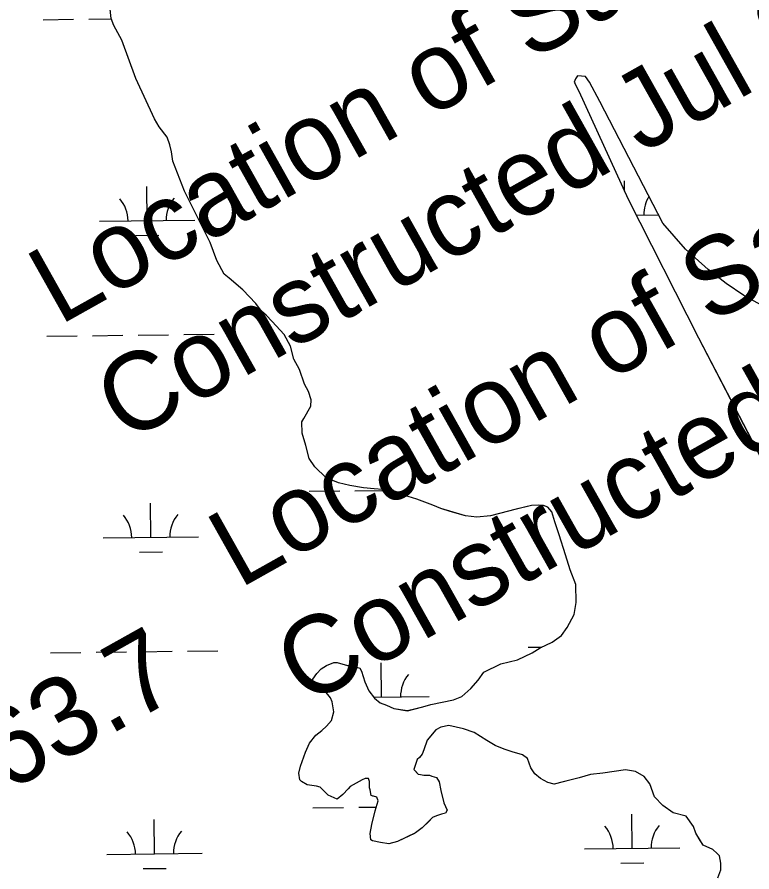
# Model space of a CAD drawing. Extents: x 3684037 to 3722149, y 433263 to 459021.
# Drawn here: x 3712807 to 3713579, y 440224 to 441123 of the extents above; entities that cross this region are included whole.
import ezdxf

# ---------------------------------------------------------------- set-up
doc = ezdxf.new("R2010")
doc.units = 0
for name, color, linetype in [('V-RIVR-RANG-IDEN', 7, 'Continuous'), ('V-RRAP-SILL-IDEN', 7, 'Continuous'), ('V-TOPO-SHOR', 7, 'Continuous'), ('V-WETL-SWMP', 7, 'Continuous')]:
    doc.layers.add(name, color=color, linetype=linetype)

msp = doc.modelspace()

# ---------------------------------------------------------------- linework, layer by layer
at = {"layer": 'V-TOPO-SHOR'}
for points in [[(3713242.08, 440400.32), (3713265.79, 440405.09), (3713274.68, 440408.66), (3713284.16, 440416.97), (3713291.86, 440425.87), (3713297.78, 440434.18), (3713315.56, 440443.1), (3713333.35, 440447.27), (3713348.76, 440454.41), (3713357.05, 440459.75), (3713369.5, 440465.7), (3713379.57, 440472.83), (3713385.5, 440481.14), (3713392.59, 440494.79), (3713394.95, 440507.24), (3713394.34, 440526.22), (3713388.39, 440541.63), (3713383.62, 440557.64), (3713377.08, 440578.39), (3713372.31, 440592.02), (3713369.34, 440602.69), (3713365.18, 440607.43), (3713360.44, 440609.21), (3713355.1, 440609.79), (3713347.98, 440609.19), (3713331.97, 440605.61), (3713314.19, 440600.85), (3713304.7, 440598.47), (3713290.47, 440597.26), (3713278.61, 440598.43), (3713262.59, 440603.16), (3713252.5, 440606.11), (3713244.2, 440609.66), (3713227.59, 440616.16), (3713209.2, 440621.48), (3713191.4, 440626.2), (3713182.5, 440626.79), (3713171.23, 440627.96), (3713157, 440630.31), (3713145.13, 440633.27), (3713132.08, 440638.59), (3713120.21, 440649.84), (3713114.27, 440658.73), (3713110.69, 440672.36), (3713107.12, 440685.41), (3713106.51, 440697.27), (3713108.88, 440700.83), (3713115.98, 440713.89), (3713116.56, 440720.41), (3713113.59, 440729.3), (3713109.43, 440737), (3713104.07, 440752.42), (3713098.13, 440763.09), (3713094.56, 440776.72), (3713088.02, 440789.17), (3713075.55, 440802.79), (3713069.01, 440809.31), (3713064.27, 440813.45), (3713058.33, 440821.75), (3713044.67, 440835.97), (3713030.42, 440848.4), (3713025.08, 440852.55), (3713017.35, 440866.77), (3713010.21, 440885.74), (3712983.46, 440939.67), (3712970.97, 440971.09), (3712969.77, 440981.17), (3712967.99, 440988.29), (3712965.01, 440996.58), (3712956.7, 441007.25), (3712951.94, 441015.55), (3712932.32, 441058.22), (3712917.45, 441098.53), (3712909.12, 441113.94), (3712906.15, 441121.05), (3712904.95, 441134.1)], [(3713588.81, 440820.1), (3713570.96, 440830.19), (3713552.5, 440842.66), (3713533.45, 440857.51), (3713509.63, 440878.89), (3713485.8, 440906.23), (3713419.62, 441034.04), (3713408.89, 441054.26), (3713404.72, 441060.2), (3713396.39, 441060.79), (3713394.02, 441057.81), (3713392.83, 441054.24), (3713393.43, 441053.05), (3713397.6, 441044.73), (3713449.49, 440931.17), (3713523.42, 440785.52), (3713627.76, 440584.58)], [(3713238.39, 440362.83), (3713234.83, 440352.71), (3713233.06, 440347.95), (3713230.09, 440344.38), (3713227.71, 440342.59), (3713225.93, 440337.23), (3713224.15, 440331.88), (3713225.94, 440330.1), (3713228.92, 440327.12), (3713231.3, 440326.53), (3713234.87, 440325.94), (3713237.84, 440325.94), (3713240.81, 440325.95), (3713243.2, 440324.76), (3713247.95, 440323.58), (3713250.93, 440318.82), (3713252.73, 440309.9), (3713255.72, 440296.82), (3713259.3, 440289.09), (3713257.52, 440286.11), (3713253.35, 440284.92), (3713248, 440283.13), (3713243.84, 440281.34), (3713243.25, 440280.74), (3713240.28, 440277.77), (3713233.15, 440270.62), (3713226.01, 440265.26), (3713224.83, 440264.66), (3713206.99, 440256.31), (3713198.07, 440253.92), (3713189.14, 440255.1), (3713180.81, 440256.87), (3713179.03, 440258.06), (3713178.43, 440264.6), (3713180.2, 440274.12), (3713183.75, 440288.4), (3713186.71, 440299.11), (3713185.52, 440302.68), (3713181.35, 440303.87), (3713179.57, 440304.46), (3713178.37, 440310.41), (3713177.77, 440312.79), (3713177.77, 440319.33), (3713176.57, 440322.3), (3713173, 440322.3), (3713170.03, 440321.1), (3713157.55, 440313.95), (3713155.17, 440311.57), (3713149.82, 440305.62), (3713143.88, 440300.85), (3713134.36, 440305), (3713130.19, 440309.16), (3713126.02, 440313.32), (3713121.85, 440314.5), (3713112.34, 440315.68), (3713106.38, 440319.24), (3713104.6, 440321.03), (3713103.4, 440328.16), (3713105.17, 440335.31), (3713110.51, 440350.18), (3713114.66, 440359.71), (3713121.2, 440368.04), (3713127.73, 440372.81), (3713132.49, 440377.57), (3713137.83, 440383.53), (3713140.2, 440392.45), (3713138.41, 440403.16), (3713136.62, 440407.32), (3713130.66, 440414.45), (3713128.87, 440415.04), (3713124.11, 440416.82), (3713118.16, 440420.98), (3713118.15, 440426.93), (3713122.31, 440432.88), (3713127.06, 440437.65), (3713132.41, 440441.22), (3713140.14, 440444.21), (3713143.71, 440444.21), (3713154.42, 440441.25), (3713156.8, 440441.25), (3713163.94, 440439.48), (3713167.51, 440438.29), (3713169.3, 440435.32), (3713172.88, 440424.02), (3713177.06, 440414.51), (3713183.02, 440406.78), (3713188.97, 440402.03), (3713195.52, 440399.66), (3713203.25, 440396.1), (3713217.53, 440393.73), (3713233.59, 440397.92), (3713242.08, 440400.32)], [(3713543.73, 440218.04), (3713546.69, 440226.38), (3713546.68, 440233.51), (3713545.48, 440241.24), (3713543.1, 440243.62), (3713538.34, 440247.78), (3713528.22, 440252.53), (3713525.24, 440257.28), (3713520.47, 440265.01), (3713518.08, 440272.15), (3713510.34, 440282.84), (3713496.65, 440286.4), (3713485.93, 440294.12), (3713477, 440303.03), (3713472.23, 440316.71), (3713466.27, 440324.43), (3713457.34, 440329.77), (3713446.63, 440331.54), (3713434.73, 440329.75), (3713422.84, 440327.95), (3713409.75, 440326.74), (3713397.86, 440323.16), (3713381.21, 440318.98), (3713371.7, 440316.59), (3713365.15, 440318.36), (3713357.41, 440322.52), (3713351.46, 440327.27), (3713347.28, 440333.81), (3713343.71, 440343.32), (3713338.35, 440347.48), (3713327.64, 440350.44), (3713319.3, 440353.41), (3713309.78, 440356.96), (3713300.85, 440362.31), (3713287.75, 440370.62), (3713276.45, 440374.77), (3713260.98, 440378.32), (3713252.65, 440376.53), (3713247.3, 440373.55), (3713238.39, 440362.83)]]:
    msp.add_lwpolyline(points, dxfattribs=at)
at = {"layer": 'V-WETL-SWMP'}
for p, q in [((3712906.15, 441121.05), (3712904.95, 441134.1)), ((3712834.77, 441119.92), (3712866.76, 441120.3)), ((3712882.76, 441120.48), (3712906.28, 441120.76)), ((3712909.13, 441113.94), (3712906.15, 441121.05)), ((3712917.45, 441098.53), (3712909.13, 441113.94)), ((3712932.32, 441058.22), (3712917.45, 441098.53)), ((3712951.94, 441015.55), (3712932.32, 441058.22)), ((3713394.02, 441057.81), (3713392.83, 441054.24)), ((3713392.83, 441054.24), (3713397.6, 441044.73)), ((3713396.39, 441060.79), (3713394.02, 441057.81)), ((3713404.72, 441060.2), (3713396.39, 441060.79)), ((3713408.89, 441054.26), (3713404.72, 441060.2)), ((3713419.62, 441034.04), (3713408.89, 441054.26)), ((3713397.6, 441044.73), (3713449.49, 440931.17)), ((3713485.81, 440906.23), (3713419.62, 441034.04)), ((3712956.7, 441007.25), (3712951.94, 441015.55)), ((3712965.01, 440996.59), (3712956.7, 441007.25)), ((3712967.99, 440988.29), (3712965.01, 440996.59)), ((3712969.78, 440981.17), (3712967.99, 440988.29)), ((3712970.97, 440971.09), (3712969.78, 440981.17)), ((3712983.47, 440939.68), (3712970.97, 440971.09)), ((3713445.66, 440939.55), (3713445.53, 440950.41)), ((3712944.08, 440908.58), (3712943.66, 440944.57)), ((3713010.22, 440885.74), (3712983.47, 440939.68)), ((3713449.49, 440931.17), (3713523.42, 440785.52)), ((3713457.92, 440914.56), (3713481.35, 440914.83)), ((3712894.08, 440907.99), (3712994.07, 440909.16)), ((3713509.63, 440878.89), (3713485.81, 440906.23)), ((3712932.26, 440893.01), (3712956.25, 440893.29)), ((3713017.36, 440866.77), (3713010.22, 440885.74)), ((3713533.45, 440857.51), (3713509.63, 440878.89)), ((3713025.08, 440852.55), (3713017.36, 440866.77)), ((3713552.5, 440842.66), (3713533.45, 440857.51)), ((3713030.42, 440848.4), (3713025.08, 440852.55)), ((3713044.67, 440835.97), (3713030.42, 440848.4)), ((3713570.96, 440830.19), (3713552.5, 440842.66)), ((3713058.33, 440821.75), (3713044.67, 440835.97)), ((3713588.82, 440820.1), (3713570.96, 440830.19)), ((3713064.27, 440813.45), (3713058.33, 440821.75)), ((3713069.02, 440809.31), (3713064.27, 440813.45)), ((3713075.55, 440802.79), (3713069.02, 440809.31)), ((3713088.02, 440789.17), (3713075.55, 440802.79)), ((3712838.64, 440787.27), (3712870.63, 440787.64)), ((3712886.63, 440787.83), (3712918.63, 440788.2)), ((3712934.63, 440788.39), (3712966.63, 440788.76)), ((3712982.63, 440788.95), (3713014.62, 440789.32)), ((3713094.56, 440776.72), (3713088.02, 440789.17)), ((3713523.42, 440785.52), (3713627.76, 440584.58)), ((3713098.13, 440763.09), (3713094.56, 440776.72)), ((3713104.07, 440752.42), (3713098.13, 440763.09)), ((3713109.43, 440737), (3713104.07, 440752.42)), ((3713113.59, 440729.3), (3713109.43, 440737)), ((3713116.57, 440720.41), (3713113.59, 440729.3)), ((3713108.88, 440700.83), (3713115.98, 440713.88)), ((3713115.98, 440713.88), (3713116.57, 440720.41)), ((3713106.51, 440697.27), (3713108.88, 440700.83)), ((3713107.12, 440685.41), (3713106.51, 440697.27)), ((3713110.69, 440672.37), (3713107.12, 440685.41)), ((3713114.27, 440658.73), (3713110.69, 440672.37)), ((3713120.21, 440649.84), (3713114.27, 440658.73)), ((3713132.08, 440638.59), (3713120.21, 440649.84)), ((3713145.14, 440633.27), (3713132.08, 440638.59)), ((3713157, 440630.31), (3713145.14, 440633.27)), ((3713114.46, 440624.29), (3713146.46, 440624.67)), ((3713171.24, 440627.96), (3713157, 440630.31)), ((3713162.46, 440624.85), (3713194.45, 440625.23)), ((3713182.5, 440626.79), (3713171.24, 440627.96)), ((3713191.4, 440626.2), (3713182.5, 440626.79)), ((3713209.2, 440621.48), (3713191.4, 440626.2)), ((3713227.59, 440616.16), (3713209.2, 440621.48)), ((3713244.2, 440609.66), (3713227.59, 440616.16)), ((3712947.95, 440575.92), (3712947.53, 440611.92)), ((3713252.51, 440606.11), (3713244.2, 440609.66)), ((3713278.61, 440598.43), (3713252.51, 440606.11)), ((3713331.98, 440605.61), (3713314.19, 440600.85)), ((3713347.98, 440609.19), (3713331.98, 440605.61)), ((3713355.1, 440609.79), (3713347.98, 440609.19)), ((3713360.44, 440609.21), (3713355.1, 440609.79)), ((3713365.18, 440607.43), (3713360.44, 440609.21)), ((3713369.34, 440602.69), (3713365.18, 440607.43)), ((3713290.47, 440597.26), (3713278.61, 440598.43)), ((3713304.7, 440598.47), (3713290.47, 440597.26)), ((3713314.19, 440600.85), (3713304.7, 440598.47)), ((3713372.32, 440592.02), (3713369.34, 440602.69)), ((3713377.08, 440578.39), (3713372.32, 440592.02)), ((3713383.63, 440557.64), (3713377.08, 440578.39)), ((3712897.95, 440575.34), (3712997.94, 440576.51)), ((3712936.13, 440560.35), (3712960.13, 440560.63)), ((3713388.39, 440541.63), (3713383.63, 440557.64)), ((3713394.34, 440526.22), (3713388.39, 440541.63)), ((3713394.96, 440507.24), (3713394.34, 440526.22)), ((3713392.6, 440494.79), (3713394.96, 440507.24)), ((3713385.5, 440481.14), (3713392.6, 440494.79)), ((3713379.58, 440472.83), (3713385.5, 440481.14)), ((3713369.5, 440465.7), (3713379.58, 440472.83)), ((3713344.38, 440460.46), (3713358.88, 440460.63)), ((3713357.06, 440459.76), (3713369.5, 440465.7)), ((3712842.51, 440454.62), (3712874.51, 440454.99)), ((3712890.5, 440455.18), (3712922.5, 440455.55)), ((3712938.5, 440455.74), (3712970.5, 440456.11)), ((3712986.5, 440456.29), (3713018.5, 440456.67)), ((3713333.35, 440447.27), (3713348.76, 440454.41)), ((3713348.76, 440454.41), (3713357.06, 440459.76)), ((3713132.41, 440441.22), (3713140.14, 440444.21)), ((3713140.14, 440444.21), (3713143.71, 440444.21)), ((3713143.71, 440444.21), (3713154.42, 440441.25)), ((3713190.39, 440407.92), (3713189.97, 440443.92)), ((3713297.78, 440434.18), (3713315.56, 440443.1)), ((3713315.56, 440443.1), (3713333.35, 440447.27)), ((3713122.31, 440432.88), (3713127.07, 440437.65)), ((3713127.07, 440437.65), (3713132.41, 440441.22)), ((3713154.42, 440441.25), (3713156.8, 440441.25)), ((3713156.8, 440441.25), (3713163.94, 440439.48)), ((3713163.94, 440439.48), (3713167.52, 440438.29)), ((3713167.52, 440438.29), (3713169.3, 440435.32)), ((3713169.3, 440435.32), (3713172.89, 440424.02)), ((3713291.86, 440425.88), (3713297.78, 440434.18)), ((3713118.16, 440426.93), (3713122.31, 440432.88)), ((3713118.16, 440420.98), (3713118.16, 440426.93)), ((3713284.16, 440416.97), (3713291.86, 440425.88)), ((3713124.12, 440416.82), (3713118.16, 440420.98)), ((3713130.66, 440414.45), (3713124.12, 440416.82)), ((3713172.89, 440424.02), (3713177.06, 440414.51)), ((3713274.68, 440408.66), (3713284.16, 440416.97)), ((3713136.62, 440407.32), (3713130.66, 440414.45)), ((3713138.41, 440403.16), (3713136.62, 440407.32)), ((3713177.06, 440414.51), (3713183.02, 440406.78)), ((3713182.21, 440407.83), (3713240.39, 440408.5)), ((3713183.02, 440406.78), (3713188.97, 440402.03)), ((3713265.79, 440405.09), (3713274.68, 440408.66)), ((3713140.21, 440392.45), (3713138.41, 440403.16)), ((3713188.97, 440402.03), (3713195.52, 440399.66)), ((3713195.52, 440399.66), (3713203.26, 440396.1)), ((3713217.54, 440393.74), (3713233.59, 440397.92)), ((3713233.59, 440397.92), (3713242.08, 440400.32)), ((3713242.08, 440400.32), (3713265.79, 440405.09)), ((3713137.84, 440383.53), (3713140.21, 440392.45)), ((3713203.26, 440396.1), (3713217.54, 440393.74)), ((3713132.49, 440377.57), (3713137.84, 440383.53)), ((3713121.2, 440368.04), (3713127.74, 440372.81)), ((3713127.74, 440372.81), (3713132.49, 440377.57)), ((3713247.3, 440373.55), (3713238.39, 440362.83)), ((3713252.65, 440376.53), (3713247.3, 440373.55)), ((3713260.98, 440378.32), (3713252.65, 440376.53)), ((3713276.45, 440374.77), (3713260.98, 440378.32)), ((3713287.76, 440370.62), (3713276.45, 440374.77)), ((3713300.85, 440362.31), (3713287.76, 440370.62)), ((3713114.67, 440359.71), (3713121.2, 440368.04)), ((3713238.39, 440362.83), (3713234.84, 440352.71)), ((3713309.78, 440356.96), (3713300.85, 440362.31)), ((3713110.51, 440350.18), (3713114.67, 440359.71)), ((3713234.84, 440352.71), (3713233.06, 440347.95)), ((3713319.31, 440353.41), (3713309.78, 440356.96)), ((3713327.64, 440350.44), (3713319.31, 440353.41)), ((3713105.18, 440335.31), (3713110.51, 440350.18)), ((3713230.09, 440344.38), (3713227.71, 440342.59)), ((3713233.06, 440347.95), (3713230.09, 440344.38)), ((3713338.35, 440347.48), (3713327.64, 440350.44)), ((3713343.71, 440343.32), (3713338.35, 440347.48)), ((3713103.4, 440328.17), (3713105.18, 440335.31)), ((3713227.71, 440342.59), (3713224.15, 440331.88)), ((3713347.29, 440333.81), (3713343.71, 440343.32)), ((3713104.6, 440321.03), (3713103.4, 440328.17)), ((3713224.15, 440331.88), (3713228.92, 440327.12)), ((3713228.92, 440327.12), (3713231.3, 440326.53)), ((3713231.3, 440326.53), (3713234.87, 440325.94)), ((3713234.87, 440325.94), (3713240.82, 440325.95)), ((3713240.82, 440325.95), (3713243.2, 440324.76)), ((3713351.46, 440327.27), (3713347.29, 440333.81)), ((3713357.41, 440322.52), (3713351.46, 440327.27)), ((3713409.76, 440326.74), (3713397.86, 440323.16)), ((3713422.84, 440327.95), (3713409.76, 440326.74)), ((3713446.63, 440331.55), (3713422.84, 440327.95)), ((3713457.34, 440329.77), (3713446.63, 440331.55)), ((3713466.27, 440324.43), (3713457.34, 440329.77)), ((3713106.39, 440319.25), (3713104.6, 440321.03)), ((3713112.34, 440315.68), (3713106.39, 440319.25)), ((3713170.03, 440321.11), (3713157.55, 440313.95)), ((3713173.01, 440322.3), (3713170.03, 440321.11)), ((3713176.58, 440322.3), (3713173.01, 440322.3)), ((3713177.77, 440319.33), (3713176.58, 440322.3)), ((3713177.78, 440312.79), (3713177.77, 440319.33)), ((3713243.2, 440324.76), (3713247.96, 440323.58)), ((3713247.96, 440323.58), (3713250.94, 440318.82)), ((3713250.94, 440318.82), (3713252.73, 440309.9)), ((3713365.15, 440318.36), (3713357.41, 440322.52)), ((3713371.7, 440316.59), (3713365.15, 440318.36)), ((3713397.86, 440323.16), (3713371.7, 440316.59)), ((3713472.23, 440316.71), (3713466.27, 440324.43)), ((3713477, 440303.03), (3713472.23, 440316.71)), ((3713121.86, 440314.51), (3713112.34, 440315.68)), ((3713126.02, 440313.32), (3713121.86, 440314.51)), ((3713134.36, 440305), (3713126.02, 440313.32)), ((3713155.17, 440311.57), (3713149.83, 440305.62)), ((3713157.55, 440313.95), (3713155.17, 440311.57)), ((3713178.37, 440310.41), (3713177.78, 440312.79)), ((3713179.57, 440304.46), (3713178.37, 440310.41)), ((3713252.73, 440309.9), (3713255.72, 440296.82)), ((3713143.88, 440300.85), (3713134.36, 440305)), ((3713149.83, 440305.62), (3713143.88, 440300.85)), ((3713185.52, 440302.68), (3713179.57, 440304.46)), ((3713183.75, 440288.4), (3713186.72, 440299.12)), ((3713186.72, 440299.12), (3713185.52, 440302.68)), ((3713485.94, 440294.12), (3713477, 440303.03)), ((3713118.33, 440291.64), (3713150.33, 440292.01)), ((3713166.33, 440292.2), (3713184.86, 440292.42)), ((3713255.72, 440296.82), (3713259.3, 440289.09)), ((3713496.65, 440286.4), (3713485.94, 440294.12)), ((3713180.2, 440274.12), (3713183.75, 440288.4)), ((3713243.84, 440281.34), (3713233.15, 440270.62)), ((3713248.01, 440283.13), (3713243.84, 440281.34)), ((3713253.36, 440284.92), (3713248.01, 440283.13)), ((3713257.52, 440286.11), (3713253.36, 440284.92)), ((3713259.3, 440289.09), (3713257.52, 440286.11)), ((3713453.69, 440249.11), (3713453.27, 440285.11)), ((3713510.34, 440282.84), (3713496.65, 440286.4)), ((3713518.09, 440272.15), (3713510.34, 440282.84)), ((3712951.82, 440243.27), (3712951.4, 440279.27)), ((3713178.43, 440264.6), (3713180.2, 440274.12)), ((3713520.47, 440265.01), (3713518.09, 440272.15)), ((3713179.03, 440258.06), (3713178.43, 440264.6)), ((3713226.02, 440265.26), (3713206.99, 440256.31)), ((3713233.15, 440270.62), (3713226.02, 440265.26)), ((3713528.22, 440252.53), (3713520.47, 440265.01)), ((3713180.82, 440256.87), (3713179.03, 440258.06)), ((3713189.15, 440255.1), (3713180.82, 440256.87)), ((3713198.07, 440253.92), (3713189.15, 440255.1)), ((3713206.99, 440256.31), (3713198.07, 440253.92)), ((3713403.7, 440248.53), (3713503.69, 440249.69)), ((3713538.34, 440247.78), (3713528.22, 440252.53)), ((3713543.1, 440243.62), (3713538.34, 440247.78)), ((3712901.82, 440242.69), (3713001.81, 440243.85)), ((3713545.49, 440241.25), (3713543.1, 440243.62)), ((3713546.68, 440233.51), (3713545.49, 440241.25)), ((3712940, 440227.7), (3712964, 440227.98)), ((3713441.87, 440233.54), (3713465.87, 440233.82)), ((3713546.69, 440226.38), (3713546.68, 440233.51)), ((3713543.73, 440218.04), (3713546.69, 440226.38))]:
    msp.add_line(p, q, dxfattribs=at)
for centre, start, end in [((3712888.83, 440908.41), 359.89487, 41.43853), ((3712999.31, 440909.69), 139.89486, 181.43852), ((3713501.18, 440915.53), 147.96321, 181.43852), ((3712892.7, 440575.76), 359.89487, 41.43853), ((3713003.18, 440577.04), 139.89486, 181.43852), ((3713245.62, 440409.04), 139.89486, 181.43852), ((3713398.45, 440248.94), 359.89487, 41.43853), ((3713508.93, 440250.23), 139.89486, 181.43852), ((3712896.57, 440243.1), 359.89487, 41.43853), ((3713007.05, 440244.39), 139.89486, 181.43852)]:
    msp.add_arc(centre, 35.25, start, end, dxfattribs=at)

# ---------------------------------------------------------------- texts
at = {"layer": 'V-RIVR-RANG-IDEN'}
msp.add_text('R-63.7', height=83, rotation=29.23958, dxfattribs=at).set_placement((3712693.5, 440249.51))
at = {"layer": 'V-RRAP-SILL-IDEN'}
for s, rotation, p in [('Location of Salt Water Barrier', 29.31036, (3712851.87, 440798.07)), ('Location of Salt Water Barrier', 29.31036, (3713040.92, 440521.42)), ('Constructed Jul 2012', 29.31036, (3712921.39, 440674.25)), ('Constructed Jul 1988', 29.31036, (3713110.43, 440397.6)), ('Location of Salt Water Barrier', 29.5409, (3713033.78, 439756.43))]:
    msp.add_text(s, height=82, rotation=rotation, dxfattribs=at).set_placement(p)

doc.saveas('drawing.dxf')
